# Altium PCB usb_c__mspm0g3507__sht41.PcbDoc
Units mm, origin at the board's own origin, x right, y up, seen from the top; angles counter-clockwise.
Board outline 68 x 40 mm, 2 copper layers (Top, Bottom), stack 0 mm thick; 37 components, 33 nets, 186 pads, 54 vias.
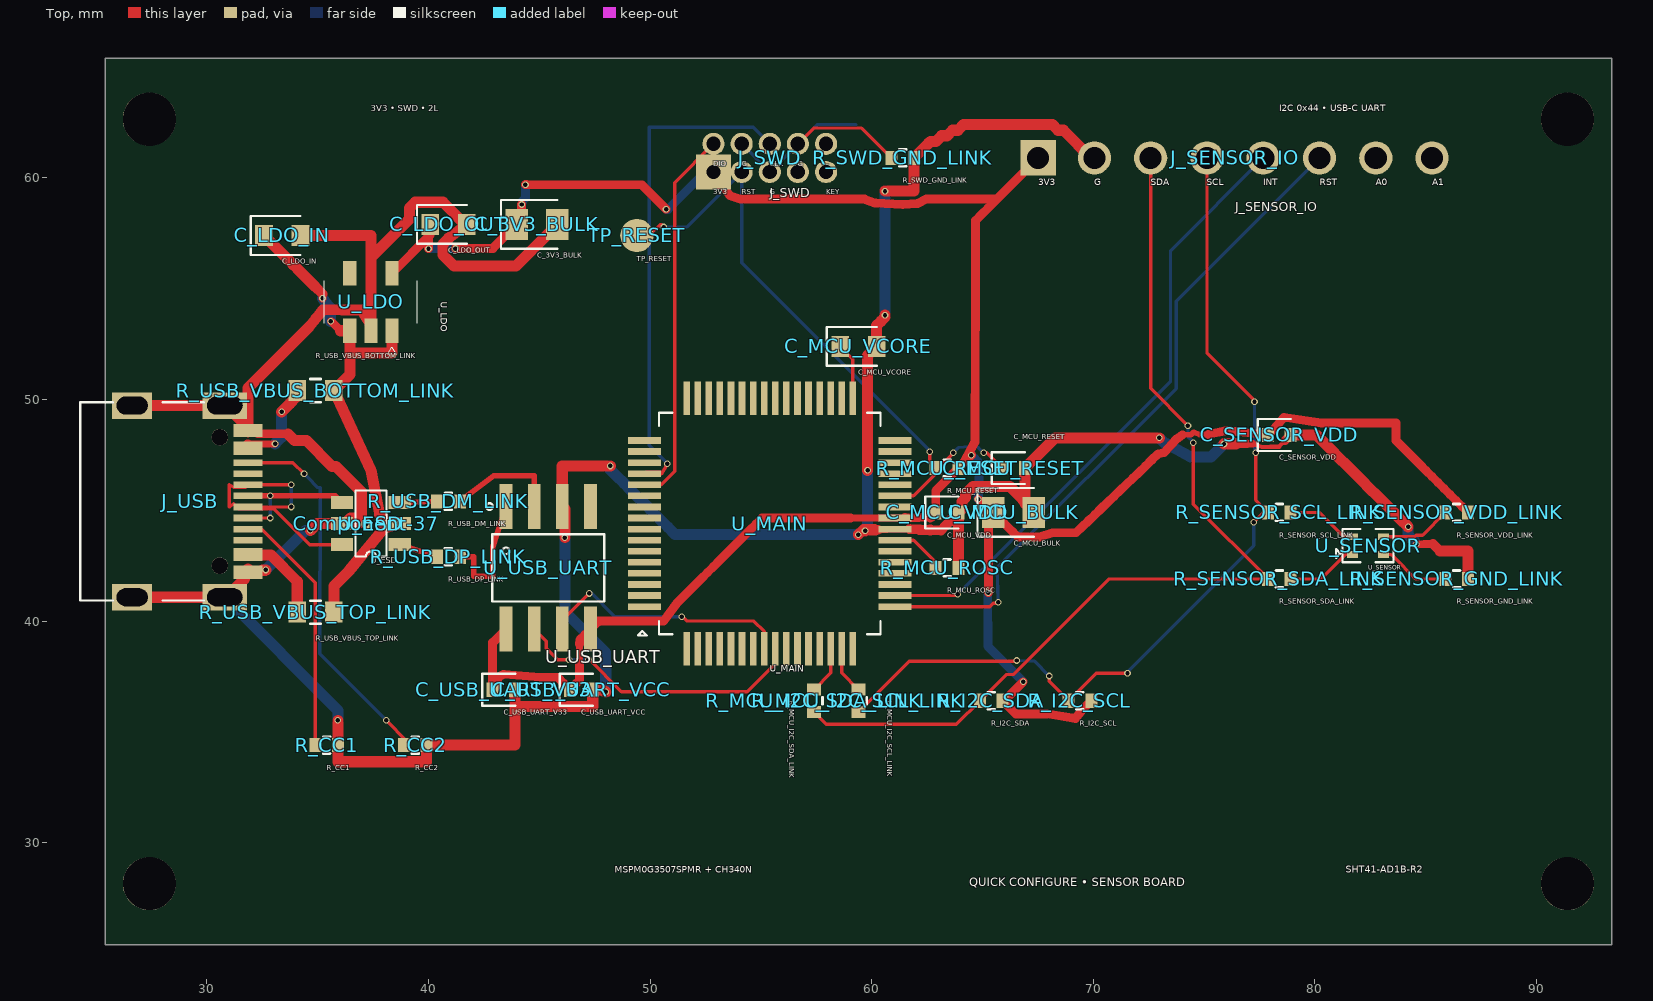
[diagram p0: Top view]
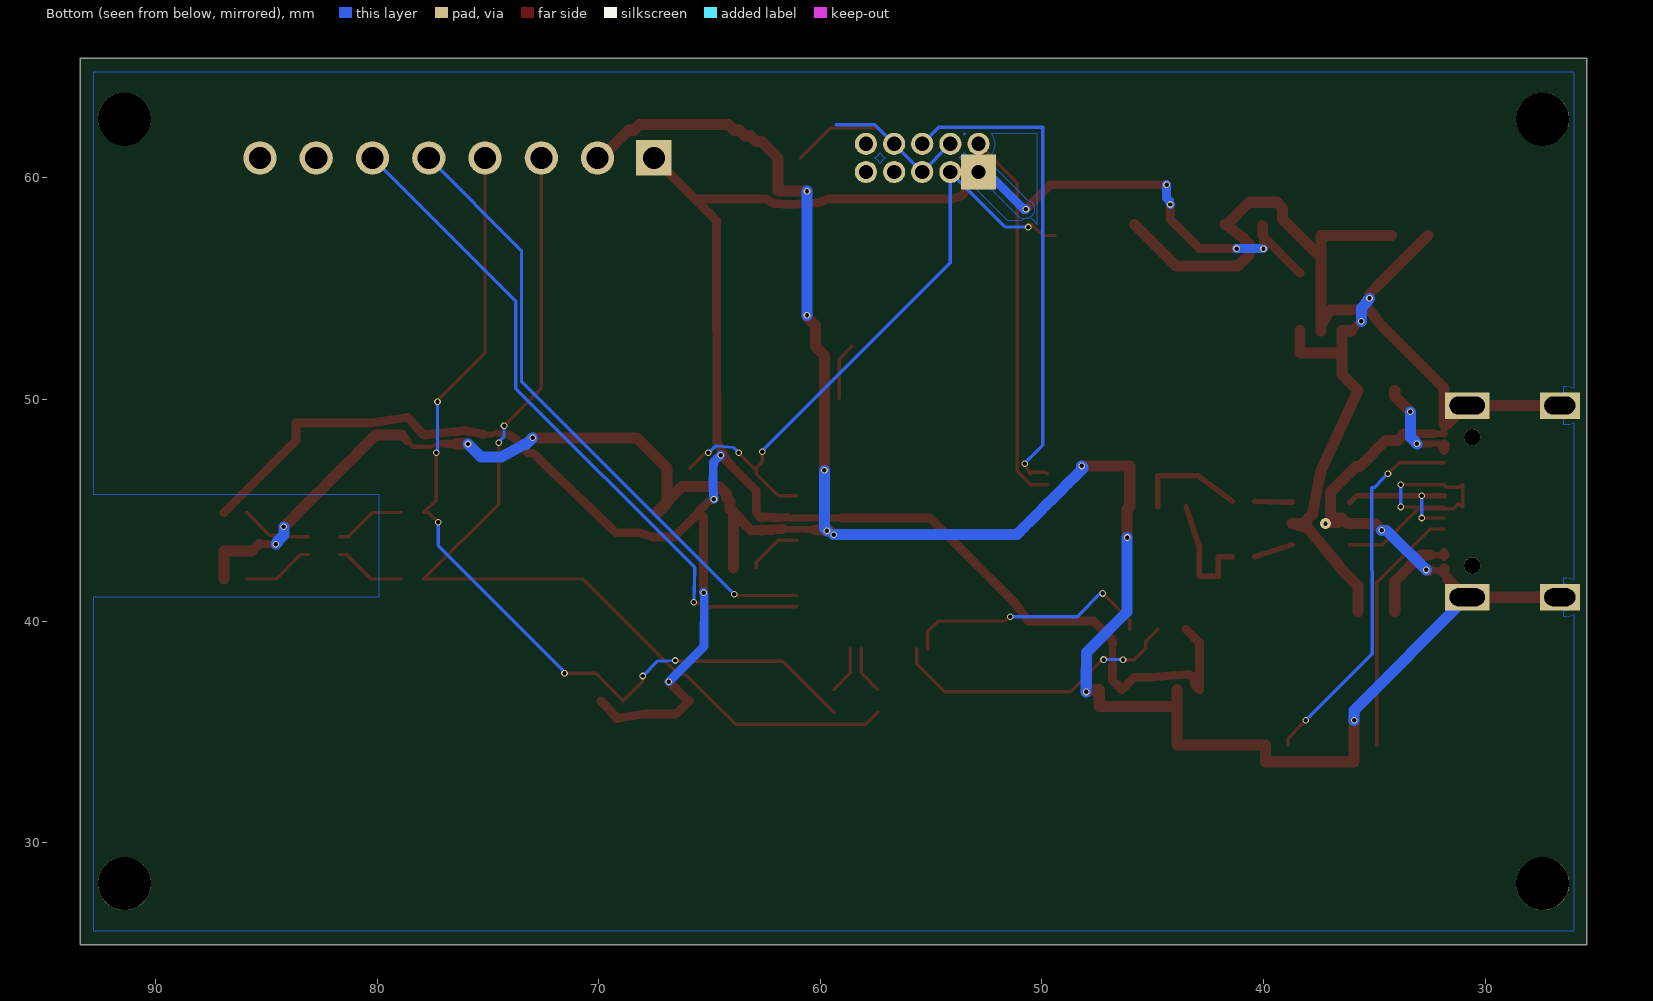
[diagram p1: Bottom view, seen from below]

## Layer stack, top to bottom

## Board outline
25.4,65.4 93.4,65.4 93.4,25.4 25.4,25.4

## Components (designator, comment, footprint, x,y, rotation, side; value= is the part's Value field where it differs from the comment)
C_3V3_BULK "" TSCIRCUIT-2.8500x1.4000mm 44.9,57.9 r0 top
C_LDO_IN "" TSCIRCUIT-2.4500x0.9500mm 33.4,57.4 r0 top
C_LDO_OUT "" TSCIRCUIT-2.4500x0.9500mm 40.9,57.9 r0 top
C_MCU_BULK "" TSCIRCUIT-2.8500x1.4000mm 66.4,44.9 r0 top
C_MCU_RESET "" TSCIRCUIT-1.5600x0.6400mm 66.4,46.9 r0 top
C_MCU_VCORE "" TSCIRCUIT-2.4500x0.9500mm 59.4,52.4 r0 top
C_MCU_VDD "" TSCIRCUIT-1.5600x0.6400mm 63.4,44.9 r0 top
C_SENSOR_VDD "" TSCIRCUIT-1.5600x0.6400mm 78.4,48.4 r0 top
C_USB_UART_V33 "" TSCIRCUIT-1.5600x0.6400mm 43.4,36.9 r0 top
C_USB_UART_VCC "" TSCIRCUIT-1.5600x0.6400mm 46.9,36.9 r0 top
Component-37 "" TSCIRCUIT-0.5000x0.5000mm 37.2,44.4 r0 top
J_SENSOR_IO "" TSCIRCUIT-19.2800x1.5000mm 76.4,60.9 r0 top
J_SWD "" TSCIRCUIT-6.0800x2.2700mm 55.4,60.9 r0 top
J_USB "" TSCIRCUIT-6.7732x9.8502mm 29.112,45.4 r90 top
R_CC1 "" TSCIRCUIT-1.5600x0.6400mm 35.4,34.4 r0 top
R_CC2 "" TSCIRCUIT-1.5600x0.6400mm 39.4,34.4 r0 top
R_I2C_SCL "" TSCIRCUIT-1.5600x0.6400mm 69.4,36.4 r0 top
R_I2C_SDA "" TSCIRCUIT-1.5600x0.6400mm 65.4,36.4 r0 top
R_MCU_I2C_SCL_LINK "" TSCIRCUIT-0.6400x1.5600mm 59.4,36.4 r270 top
R_MCU_I2C_SDA_LINK "" TSCIRCUIT-0.6400x1.5600mm 57.4,36.4 r270 top
R_MCU_RESET "" TSCIRCUIT-1.5600x0.6400mm 63.4,46.9 r0 top
R_MCU_ROSC "" TSCIRCUIT-1.5600x0.6400mm 63.4,42.4 r0 top
R_SENSOR_GND_LINK "" TSCIRCUIT-1.5600x0.6400mm 86.4,41.9 r0 top
R_SENSOR_SCL_LINK "" TSCIRCUIT-1.5600x0.6400mm 78.4,44.9 r0 top
R_SENSOR_SDA_LINK "" TSCIRCUIT-1.5600x0.6400mm 78.4,41.9 r0 top
R_SENSOR_VDD_LINK "" TSCIRCUIT-1.5600x0.6400mm 86.4,44.9 r0 top
R_SWD_GND_LINK "" TSCIRCUIT-1.5600x0.6400mm 61.4,60.9 r0 top
R_USB_DM_LINK "" TSCIRCUIT-1.5600x0.6400mm 40.9,45.4 r0 top
R_USB_DP_LINK "" TSCIRCUIT-1.5600x0.6400mm 40.9,42.9 r0 top
R_USB_VBUS_BOTTOM_LINK "" TSCIRCUIT-2.4500x0.9500mm 34.9,50.4 r0 top
R_USB_VBUS_TOP_LINK "" TSCIRCUIT-2.4500x0.9500mm 34.9,40.4 r0 top
TP_RESET "" TSCIRCUIT-1.5000x1.5000mm 49.4,57.4 r0 top
U_ESD "" TSCIRCUIT-3.6000x2.5000mm 37.4,44.4 r0 top
U_LDO "" TSCIRCUIT-2.5000x3.7000mm 37.4,54.4 r270 top
U_MAIN "" TSCIRCUIT-12.8000x12.8000mm 55.4,44.4 r0 top
U_SENSOR "" TSCIRCUIT-1.9000x1.1001mm 82.4,43.4 r0 top
U_USB_UART "" TSCIRCUIT-4.3840x7.5712mm 45.4,42.4 r0 top

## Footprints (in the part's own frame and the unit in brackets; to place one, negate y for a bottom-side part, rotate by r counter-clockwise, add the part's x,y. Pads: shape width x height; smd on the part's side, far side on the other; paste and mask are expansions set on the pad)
TSCIRCUIT-0.5000x0.5000mm [mm]
TSCIRCUIT-0.6400x1.5600mm [mm]
  rect 0.54x0.64 smd: 1(-0.51,0) 2(0.51,0)
  silkscreen extent -0.15,-0.38 0.15,0.38
TSCIRCUIT-1.5000x1.5000mm [mm]
  round 1.5 smd: 1(0,0)
TSCIRCUIT-1.5600x0.6400mm [mm]
  rect 0.54x0.64 smd: 1(-0.51,0) 2(0.51,0)
  silkscreen extent -0.98,-0.72 0.51,0.72
TSCIRCUIT-1.9000x1.1001mm [mm]
  rect 0.5x0.3 smd: 1(-0.7,-0.4) 2(-0.7,0.4) 3(0.7,0.4) 4(0.7,-0.4)
  silkscreen extent -1.45,-0.75 1.15,0.75
TSCIRCUIT-2.4500x0.9500mm [mm]
  rect 0.8x0.95 smd: 1(-0.825,0) 2(0.825,0)
  silkscreen extent -1.42,-0.87 0.82,0.87
TSCIRCUIT-2.5000x3.7000mm [mm]
  rect 1.1x0.6 smd: 1(1.3,0.95) 2(1.3,0) 3(1.3,-0.95) 4(-1.3,-0.95) 5(-1.3,0.95)
  silkscreen extent -0.95,-2.1 2.35,2.1
TSCIRCUIT-2.8500x1.4000mm [mm]
  rect 1.025x1.4 smd: 1(-0.913,0) 2(0.913,0)
  silkscreen extent -1.62,-1.1 0.91,1.1
TSCIRCUIT-3.6000x2.5000mm [mm]
  rect 1x0.6 smd: 1(-1.3,-0.95) 2(-1.3,0) 3(-1.3,0.95) 4(1.3,0.95) 5(1.3,0) 6(1.3,-0.95)
  silkscreen extent -0.7,-1.49 0.7,1.49
TSCIRCUIT-4.3840x7.5712mm [mm]
  rect 0.574x2.036 smd: 1(-1.905,2.768) 2(-0.635,2.768) 3(0.635,2.768) 4(1.905,2.768) 5(1.905,-2.768) 6(0.635,-2.768) 7(-0.635,-2.768) 8(-1.905,-2.768)
  silkscreen extent -2.79,-1.52 2.53,2.92
TSCIRCUIT-6.0800x2.2700mm [mm]
  rect 1.6x1.6 hole 0.65: 1(-2.54,-0.635)
  round 1 hole 0.65: 2(-2.54,0.635) 3(-1.27,0.635) 4(0,0.635) 5(1.27,0.635) 6(2.54,0.635) 7(2.54,-0.635) 8(1.27,-0.635) 9(0,-0.635) 10(-1.27,-0.635)
TSCIRCUIT-6.7732x9.8502mm [mm]
  rect 0.3x1.3 smd: 1(-3.35,-2.737) 2(-3.05,-2.737) 3(-2.55,-2.737) 4(-2.25,-2.737) 5(-1.75,-2.737) 6(-1.25,-2.737) 7(-0.75,-2.737) 8(-0.25,-2.737) 9(0.25,-2.737) 10(0.75,-2.737) 11(1.25,-2.737) 12(1.75,-2.737) 13(2.55,-2.737) 14(2.25,-2.737) 15(3.35,-2.737) 16(3.05,-2.737)
  rect 1.2x2 hole 0.8 slot 1.6 at 90 deg: 17(-4.325,-1.693) 18(4.325,-1.693)
  rect 1.2x1.8 hole 0.8 slot 1.4 at 90 deg: 19(4.325,2.487) 20(-4.325,2.487)
  round 0.75 hole 0.75 unplated: NPTH-1(-2.9,-1.468) NPTH-2(2.9,-1.468)
  silkscreen extent -4.47,-0.75 4.47,4.83
TSCIRCUIT-12.8000x12.8000mm [mm]
  rect 1.5x0.3 smd: 1(-5.65,-3.75) 2(-5.65,-3.25) 3(-5.65,-2.75) 4(-5.65,-2.25) 5(-5.65,-1.75) 6(-5.65,-1.25) 7(-5.65,-0.75) 8(-5.65,-0.25) 9(-5.65,0.25) 10(-5.65,0.75) 11(-5.65,1.25) 12(-5.65,1.75) 13(-5.65,2.25) 14(-5.65,2.75) 15(-5.65,3.25) 16(-5.65,3.75) 33(5.65,3.75) 34(5.65,3.25) 35(5.65,2.75) 36(5.65,2.25) 37(5.65,1.75) 38(5.65,1.25) 39(5.65,0.75) 40(5.65,0.25) 41(5.65,-0.25) 42(5.65,-0.75) 43(5.65,-1.25) 44(5.65,-1.75) 45(5.65,-2.25) 46(5.65,-2.75) 47(5.65,-3.25) 48(5.65,-3.75)
  rect 0.3x1.5 smd: 17(-3.75,5.65) 18(-3.25,5.65) 19(-2.75,5.65) 20(-2.25,5.65) 21(-1.75,5.65) 22(-1.25,5.65) 23(-0.75,5.65) 24(-0.25,5.65) 25(0.25,5.65) 26(0.75,5.65) 27(1.25,5.65) 28(1.75,5.65) 29(2.25,5.65) 30(2.75,5.65) 31(3.25,5.65) 32(3.75,5.65) 49(3.75,-5.65) 50(3.25,-5.65) 51(2.75,-5.65) 52(2.25,-5.65) 53(1.75,-5.65) 54(1.25,-5.65) 55(0.75,-5.65) 56(0.25,-5.65) 57(-0.25,-5.65) 58(-0.75,-5.65) 59(-1.25,-5.65) 60(-1.75,-5.65) 61(-2.25,-5.65) 62(-2.75,-5.65) 63(-3.25,-5.65) 64(-3.75,-5.65)
  silkscreen extent -5.95,-5.05 5,5
TSCIRCUIT-19.2800x1.5000mm [mm]
  rect 1.6x1.6 hole 1: 1(-8.89,0)
  round 1.5 hole 1: 2(-6.35,0) 3(-3.81,0) 4(-1.27,0) 5(1.27,0) 6(3.81,0) 7(6.35,0) 8(8.89,0)

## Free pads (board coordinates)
  round 2.4 hole 2.4 unplated: NPTH-3(27.4,28.15) NPTH-4(91.4,28.15) NPTH-5(27.4,62.65) NPTH-6(91.4,62.65)

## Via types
v1: diameter 0.3, hole 0.2, Top to Bottom, 53 vias
v2: diameter 0.5, hole 0.2, Top to Bottom, 1 vias

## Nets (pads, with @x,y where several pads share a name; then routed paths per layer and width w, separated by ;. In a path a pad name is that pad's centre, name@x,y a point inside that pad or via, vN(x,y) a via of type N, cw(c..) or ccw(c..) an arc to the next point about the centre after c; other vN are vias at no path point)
".J_SWD > .pin2 to .U_MAIN > .pin12": J_SWD.2 U_MAIN.12 | length 17.1
  Top w0.15: U_MAIN.12 50.495,46.15 51.111,46.762 51.11,59.781 J_SWD.2
".J_SWD > .pin4 to .U_MAIN > .pin13": J_SWD.4 U_MAIN.13 | length 22.7
  Top w0.15: U_MAIN.13 49.819,46.719 50.52,46.719 50.509,46.646 50.708,46.977 v1(50.771,47.106)
  Bottom w0.15: v1(50.771,47.106) 50.77,47.112 49.959,47.923 49.959,62.28 54.655,62.28 J_SWD.4
".U_MAIN > .pin42 to .R_MCU_ROSC > .pin1": R_MCU_ROSC.1 U_MAIN.42 | length 2.5
  Top w0.15: U_MAIN.42 61.89,43.65 62.89,42.65 R_MCU_ROSC.1
GND: C_3V3_BULK.2 C_LDO_IN.2 C_LDO_OUT.2 C_MCU_BULK.2 C_MCU_RESET.2 C_MCU_VCORE.2 C_MCU_VDD.2 C_SENSOR_VDD.2 C_USB_UART_V33.2 C_USB_UART_VCC.2 J_SENSOR_IO.2 J_USB.1 J_USB.2 J_USB.15 J_USB.16 J_USB.17 J_USB.18 J_USB.19 J_USB.20 R_CC1.2 R_CC2.2 R_MCU_ROSC.2 R_SENSOR_GND_LINK.2 R_SWD_GND_LINK.2 U_ESD.2 U_LDO.2 U_MAIN.41 U_USB_UART.3 | length 181.2
  Top w0.188: 77.2,48 77.618,47.858 78.001,47.866
  Top w0.2: 78.001,47.866 78.384,47.874 C_SENSOR_VDD.2@78.647,48.137
  Top w0.275: J_USB.16 J_USB.16@32.299,48.45
  Top w0.3: J_USB.1@31.699,41.9 J_USB.1 J_USB.1@31.849,42.2 ; J_USB.15@31.699,48.9 J_USB.15 ; J_USB.2 31.996,42.25 32.076,42.25 32.118,42.292 J_USB.2@32.499,42.292 ; J_USB.16@31.849,48.6 J_USB.15 ; J_USB.15@31.849,48.9 J_USB.15 ; 60.113,44.15 60.582,44.15 U_MAIN.41 61.144,44.15 61.238,44.15 61.331,44.15 61.425,44.15 61.519,44.15 61.613,44.15 U_MAIN.41@61.706,44.15
  Top w0.301: U_MAIN.41@60.3,44.118 60.425,44.118 60.55,44.118 60.675,44.118 U_MAIN.41
  Top w0.325: J_USB.16 J_USB.16@31.849,48.6
  Top w0.337: 76.936,48.001 77.2,48
  Top w0.35: v1(84.573,43.468) 84.952,43.473 85.331,43.479
  Top w0.375: J_USB.16@32.299,48.45 32.749,48.45 33.199,48.45 ; 76.437,48.001 76.936,48.001
  Top w0.4: 33.199,48.45 33.649,48.45 ; 36.6,44.4 37.2,44.4 ; 60.175,44.118 60.3,44.118 ; C_SENSOR_VDD.2@78.647,48.137 C_SENSOR_VDD.2
  Top w0.437: 63.119,44.087 63.338,44.306 63.556,44.525
  Top w0.45: U_MAIN.41@61.706,44.15 62.177,44.129 ; 62.648,44.108 63.119,44.087 ; 85.331,43.479 85.647,43.163
  Top w0.475: 34.92,53.66 35.228,54.041 35.666,54.041 36.103,54.041 ; v1(59.397,43.902) 59.401,43.907 59.645,44.15 60.113,44.15 ; 62.177,44.129 62.648,44.108
  Top w0.481: 34.613,53.279 34.92,53.66
  Top w0.5: J_USB.20 J_USB.17 ; J_USB.19 J_USB.18 ; J_USB.17 30.874,41.075 31.474,41.675 31.699,41.9 ; J_USB.18 30.874,49.725 31.474,49.125 31.699,48.9 ; J_USB.1@31.849,42.2 J_USB.2 ; 31.849,48.9 31.849,50.516 34.613,53.279 ; 32.499,42.292 32.64,42.292 v1(32.653,42.306) ; 33.649,48.45 33.949,48.15 34.483,48.15 35.65,46.983 35.817,46.983 36.983,45.817 36.983,44.817 36.817,44.65 36.483,44.65 36.233,44.4 U_ESD.2 34.977,44.4 v1(34.668,44.091) ; C_LDO_IN.2 37.4,57.4 U_LDO.2 ; v1(35.91,35.52) 35.91,35.4 R_CC1.2 35.91,33.65 39.91,33.65 R_CC2.2 43.91,34.4 C_USB_UART_V33.2 43.91,36.15 47.41,36.15 C_USB_UART_VCC.2 47.826,36.9 47.885,36.841 47.959,36.841 v1(48,36.8) ; 36.103,54.041 36.541,54.041 36.978,54.041 37.189,53.713 37.4,53.384 U_LDO.2 ; C_3V3_BULK.2 43.937,56.025 41.15,56.025 40.65,56.525 40.65,57.025 40.9,57.275 C_LDO_OUT.2 41.65,57.9 40.65,58.9 39.4,58.9 39.15,58.65 39.15,58.15 37.65,56.65 37.4,56.4 U_LDO.2 ; v1(46.15,43.767) 46.15,45.053 U_USB_UART.3 46.035,47 v1(48.2,47) ; v1(59.7,44.075) 59.645,44.118 60.05,44.118 60.175,44.118 ; v1(59.813,46.799) 59.816,46.802 59.816,46.82 59.816,51.991 C_MCU_VCORE.2 60.225,52.871 60.225,53.342 60.413,53.529 60.6,53.717 v1(60.6,53.8) ; v1(60.6,59.4) 61.91,59.4 R_SWD_GND_LINK.2 62.241,61.231 62.571,61.561 62.65,61.64 62.65,61.65 62.9,61.65 63.15,61.9 63.4,61.9 63.65,62.15 63.9,62.15 64.15,62.4 68.15,62.4 68.4,62.15 68.65,62.15 69.9,60.9 J_SENSOR_IO.2 ; 63.556,44.525 63.66,44.65 C_MCU_VDD.2 ; R_MCU_ROSC.2 C_MCU_VDD.2 ; v1(72.984,48.267) 72.513,48.267 72.043,48.267 71.572,48.267 71.101,48.267 70.63,48.267 70.16,48.267 69.689,48.267 69.218,48.267 68.748,48.267 68.277,48.267 67.935,47.925 67.593,47.583 67.252,47.242 C_MCU_RESET.2 66.91,45.303 C_MCU_BULK.2 67.312,44.988 66.233,46.067 64.567,46.067 64.233,45.733 64.233,45.567 64.067,45.4 64.067,45.067 63.9,44.9 C_MCU_VDD.2 ; v1(75.9,47.99) 75.91,48 75.936,48 75.938,48.001 76.437,48.001 ; C_SENSOR_VDD.2 79.295,48.4 79.68,48.4 80.065,48.4 80.409,48.056 80.753,47.712 81.098,47.367 81.442,47.023 81.786,46.679 82.13,46.335 82.475,45.99 82.819,45.646 83.163,45.302 83.507,44.958 83.851,44.613 84.196,44.269 84.196,44.265 v1(84.212,44.249) ; 85.647,43.163 86.91,43.163 R_SENSOR_GND_LINK.2
  Bottom w0.5: J_USB.17 35.91,35.971 v1(35.91,35.52) ; v1(32.653,42.306) 34.438,44.091 v1(34.668,44.091) ; v1(46.15,43.767) 46.15,40.419 47.994,38.575 47.996,38.131 47.997,37.687 47.999,37.244 v1(48,36.8) ; v1(48.2,47) 48.151,46.951 48.151,46.883 48.482,46.551 48.813,46.22 49.144,45.889 49.476,45.558 49.807,45.227 50.138,44.895 50.469,44.564 50.8,44.233 51.132,43.902 51.618,43.902 52.104,43.902 52.59,43.902 53.076,43.902 53.562,43.902 54.049,43.902 54.535,43.902 55.021,43.902 55.507,43.902 55.993,43.902 56.48,43.902 56.966,43.902 57.452,43.902 57.938,43.902 58.424,43.902 58.911,43.902 v1(59.397,43.902) ; v1(59.7,44.075) 59.813,44.188 v1(59.813,46.799) ; v1(60.6,53.8) 60.6,54.291 60.6,54.782 60.6,55.272 60.6,55.763 60.6,56.254 60.6,56.745 60.6,57.236 60.6,57.726 60.6,58.217 60.6,58.708 60.6,59.199 v1(60.6,59.4) ; v1(72.984,48.267) 73.274,47.977 73.339,47.977 74.4,47.4 75.31,47.4 v1(75.9,47.99) ; v1(84.212,44.249) 84.212,43.885 84.484,43.613 84.484,43.566 v1(84.573,43.468)
MAIN_RESET: C_MCU_RESET.1 J_SWD.10 R_MCU_RESET.1 TP_RESET.1 U_MAIN.38 | length 29.3
  Top w0.15: TP_RESET.1 49.961,57.4 50.448,57.887 50.514,57.887 v1(50.621,57.78) ; U_MAIN.38 61.889,45.65 62.89,46.651 R_MCU_RESET.1@62.89,46.9 ; v1(62.615,47.635) 62.615,47.175 R_MCU_RESET.1 63.006,46.9 63.631,47.525 63.631,47.544 v1(63.678,47.591) ; v1(65.057,47.593) 65.192,47.598 C_MCU_RESET.1
  Bottom w0.15: v1(50.621,57.78) 51.645,57.78 J_SWD.10 54.13,56.173 62.549,47.754 62.549,47.701 v1(62.615,47.635) ; v1(63.678,47.591) 63.915,47.829 64.661,47.898 64.82,47.83 64.82,47.812 64.984,47.648 v1(65.057,47.593)
MCU_I2C_SCL_LOCAL: R_MCU_I2C_SCL_LINK.1 U_MAIN.50 | length 2.2
  Top w0.15: U_MAIN.50 58.65,37.66 R_MCU_I2C_SCL_LINK.1
MCU_I2C_SDA_LOCAL: R_MCU_I2C_SDA_LINK.1 U_MAIN.51 | length 2.2
  Top w0.15: R_MCU_I2C_SDA_LINK.1 58.15,37.66 U_MAIN.51
MSPM0_VCORE: C_MCU_VCORE.1 U_MAIN.32 | length 2.6
  Top w0.15: C_MCU_VCORE.1 59.15,51.825 U_MAIN.32
SENSOR_ADDR0: J_SENSOR_IO.7
SENSOR_ADDR1: J_SENSOR_IO.8
SENSOR_INT: J_SENSOR_IO.5 U_MAIN.47 | length 28.3
  Top w0.15: U_MAIN.47 63.75,41.15 63.785,41.185 63.858,41.185 v1(63.876,41.203)
  Bottom w0.15: v1(63.876,41.203) 73.486,50.816 73.488,56.719 J_SENSOR_IO.5
SENSOR_RESET: J_SENSOR_IO.6 U_MAIN.48 | length 30.8
  Top w0.15: U_MAIN.48 65.331,40.65 65.486,40.805 65.636,40.805 v1(65.704,40.841)
  Bottom w0.15: v1(65.704,40.841) 65.672,42.417 73.751,50.494 73.752,54.439 J_SENSOR_IO.6
SENSOR_SCL: J_SENSOR_IO.4 R_I2C_SCL.1 R_MCU_I2C_SCL_LINK.2 R_SENSOR_SCL_LINK.1 | length 41.7
  Top w0.15: R_MCU_I2C_SCL_LINK.2 61.69,38.18 66.276,38.18 66.505,38.18 v1(66.544,38.219) ; v1(68.01,37.52) 68.01,37.28 R_I2C_SCL.1 70.128,37.638 v1(71.544,37.638) ; J_SENSOR_IO.4 75.13,52.109 77.223,50.017 77.223,49.953 v1(77.276,49.9) ; v1(77.248,44.458) 77.306,44.516 77.69,44.9 R_SENSOR_SCL_LINK.1 77.329,45.461 v1(77.329,47.589)
  Bottom w0.15: v1(66.544,38.219) 67.348,38.182 67.989,37.541 v1(68.01,37.52) ; v1(71.544,37.638) 71.628,37.722 71.628,37.787 77.248,43.406 v1(77.248,44.458) ; v1(77.276,49.9) 77.276,47.706 77.315,47.667 77.315,47.603 v1(77.329,47.589)
SENSOR_SDA: J_SENSOR_IO.3 R_I2C_SDA.1 R_MCU_I2C_SDA_LINK.2 R_SENSOR_SDA_LINK.1 | length 44.6
  Top w0.15: R_MCU_I2C_SDA_LINK.2 57.953,35.337 63.827,35.337 R_I2C_SDA.1 66.076,37.586 66.398,37.586 70.713,41.9 R_SENSOR_SDA_LINK.1 74.513,45.277 v1(74.513,48.04) ; J_SENSOR_IO.3 72.59,50.499 74.251,48.838 v1(74.273,48.816)
  Bottom w0.15: v1(74.273,48.816) 74.273,48.328 74.457,48.143 74.457,48.096 v1(74.513,48.04)
SHT_GND_LOCAL: R_SENSOR_GND_LINK.1 U_SENSOR.4 | length 3.2
  Top w0.15: U_SENSOR.4 83.44,43 83.551,42.891 84.542,41.9 R_SENSOR_GND_LINK.1
SHT_SCL_LOCAL: R_SENSOR_SCL_LINK.2 U_SENSOR.2 | length 3.2
  Top w0.15: R_SENSOR_SCL_LINK.2 80.201,44.9 81.232,43.868 81.291,43.81 81.36,43.8 U_SENSOR.2
SHT_SDA_LOCAL: R_SENSOR_SDA_LINK.2 U_SENSOR.1 | length 3.3
  Top w0.15: R_SENSOR_SDA_LINK.2 80.281,41.9 81.256,42.875 81.313,42.933 81.36,43 U_SENSOR.1
SHT_VDD_LOCAL: R_SENSOR_VDD_LINK.1 U_SENSOR.3 | length 3.2
  Top w0.15: U_SENSOR.3 83.44,43.8 83.5,43.801 83.6,43.801 84.499,43.812 84.571,43.87 84.86,43.87 R_SENSOR_VDD_LINK.1
swd-ground-1-to-2: J_SWD.3 J_SWD.5 J_SWD.9 R_SWD_GND_LINK.1 | length 14.6
  Top w0.15: J_SWD.5 57.382,62.247 59.375,62.247 59.543,62.247 R_SWD_GND_LINK.1
  Bottom w0.15: J_SWD.3 J_SWD.9 57.54,62.405 ; J_SWD.5 57.54,62.405 ; 57.54,62.405 59.277,62.405 57.54,62.405
UART_MSP_RX: U_MAIN.57 U_USB_UART.6 | length 11.5
  Top w0.15: U_USB_UART.6 46.035,40.034 v1(47.247,41.246) ; v1(51.43,40.198) 51.459,40.169 51.5,40.169 51.669,40 54.679,40 55.15,39.529 U_MAIN.57
  Bottom w0.15: v1(47.247,41.246) 47.292,41.291 47.318,41.291 48.411,40.198 v1(51.43,40.198)
UART_MSP_TX: U_MAIN.56 U_USB_UART.7 | length 13.5
  Top w0.15: U_USB_UART.7 45.314,39.083 45.314,38.765 45.83,38.249 v1(46.338,38.249) ; v1(47.217,38.262) 47.194,38.265 47.247,38.265 48.707,36.806 54.392,36.806 55.65,38.064 U_MAIN.56
  Bottom w0.15: v1(46.338,38.249) 46.348,38.259 46.444,38.259 46.447,38.262 v1(47.217,38.262)
usb-dm-device: R_USB_DM_LINK.1 U_ESD.4 | length 1.7
  Top w0.25: U_ESD.4 R_USB_DM_LINK.1
usb-dm-port-tie: J_USB.7 J_USB.9 U_ESD.3 | length 7.4
  Top w0.15: J_USB.7 v1(32.85,44.65) ; J_USB.9 v1(32.85,45.65)
  Top w0.25: J_USB.9 35.8,45.65 U_ESD.3
  Bottom w0.15: v1(32.85,44.65) v1(32.85,45.65)
usb-dm-uart: R_USB_DM_LINK.2 U_USB_UART.2 | length 5.1
  Top w0.25: R_USB_DM_LINK.2 42.95,46.55 44.765,46.55 U_USB_UART.2
usb-dp-device: R_USB_DP_LINK.1 U_ESD.6 | length 1.8
  Top w0.25: U_ESD.6 R_USB_DP_LINK.1
usb-dp-port-tie: J_USB.8 J_USB.10 U_ESD.1 | length 12.7
  Top w0.15: J_USB.8 v1(33.8,45.15) ; v1(33.8,46.15) J_USB.10 31.742,46.043 31.199,46.043 31.013,46.15 31.013,45.15 31.199,45.293 31.427,45.066 33.019,45.066 34.635,43.45 U_ESD.1
  Bottom w0.15: v1(33.8,45.15) v1(33.8,46.15)
usb-dp-uart: R_USB_DP_LINK.2 U_USB_UART.1 | length 5.6
  Top w0.25: R_USB_DP_LINK.2 42.05,42.9 42.05,42.03 42.9,42.03 42.9,43.35 U_USB_UART.1
USB_CC1: J_USB.6 R_CC1.1 | length 11.4
  Top w0.15: J_USB.6 32.463,44.15 34.89,41.723 R_CC1.1
USB_CC2: J_USB.12 R_CC2.1 | length 16.9
  Top w0.15: J_USB.12 33.879,47.15 v1(34.382,46.647) ; v1(38.09,35.52) 38.232,35.378 38.89,34.72 R_CC2.1
  Bottom w0.15: v1(34.382,46.647) 34.542,46.487 34.545,46.487 35.007,46.025 35.112,46.025 35.095,38.524 v1(38.09,35.52)
USB_VBUS_BOTTOM_LOCAL: J_USB.13 J_USB.14 R_USB_VBUS_BOTTOM_LINK.1 | length 4.4
  Top w0.3: J_USB.14 J_USB.14@31.849,47.8 ; J_USB.13 31.893,47.994 32.286,47.994 J_USB.13@32.499,47.994
  Top w0.325: 32.499,47.994 32.68,47.994 v1(33.073,47.994)
  Top w0.475: J_USB.13@31.849,47.8 J_USB.13
  Top w0.5: v1(33.372,49.443) 33.395,49.466 33.735,49.806 34.075,50.146 R_USB_VBUS_BOTTOM_LINK.1
  Bottom w0.5: v1(33.073,47.994) 33.124,48.045 33.124,48.047 33.372,48.295 33.372,48.678 33.372,49.06 v1(33.372,49.443)
USB_VBUS_TOP_LOCAL: J_USB.3 J_USB.4 R_USB_VBUS_TOP_LINK.1 | length 4.5
  Top w0.3: J_USB.3@31.849,42.965 J_USB.3 31.849,43 J_USB.4
  Top w0.318: J_USB.3@31.849,42.965 J_USB.3@32.499,42.974
  Top w0.5: 32.499,42.974 32.887,42.98 34.075,41.792 R_USB_VBUS_TOP_LINK.1
VBUS5: C_LDO_IN.1 R_USB_VBUS_BOTTOM_LINK.2 R_USB_VBUS_TOP_LINK.2 U_ESD.5 U_LDO.1 U_LDO.3 | length 25.5
  Top w0.325: v1(35.584,53.531) 35.601,53.514 v1@35.622,53.514
  Top w0.35: v1(35.214,54.561) 35.214,54.761
  Top w0.375: v1@35.622,53.514 35.829,53.307 36.036,53.1
  Top w0.45: 34.884,55.091 35.214,54.761
  Top w0.5: C_LDO_IN.1 32.905,57.07 33.235,56.74 33.565,56.41 33.894,56.08 34.224,55.751 34.554,55.421 34.884,55.091 ; R_USB_VBUS_TOP_LINK.2 35.725,40.793 35.725,41.185 35.725,41.578 36.069,41.922 36.413,42.266 38,44.2 U_ESD.5 38.2,44.4 37.8,44.8 37.4,46.8 R_USB_VBUS_BOTTOM_LINK.2 36.45,51.125 U_LDO.3 ; 36.036,53.1 U_LDO.3 ; U_LDO.1 38.35,52.1 36.45,52.1 U_LDO.3
  Bottom w0.5: v1(35.214,54.561) 35.304,54.471 35.304,54.414 35.584,54.134 35.584,53.832 v1(35.584,53.531)
VCC_3V3: C_3V3_BULK.1 C_LDO_OUT.1 C_MCU_BULK.1 C_MCU_VDD.1 C_SENSOR_VDD.1 C_USB_UART_V33.1 C_USB_UART_VCC.1 J_SENSOR_IO.1 J_SWD.1 R_I2C_SCL.2 R_I2C_SDA.2 R_MCU_RESET.2 R_SENSOR_VDD_LINK.2 U_LDO.5 U_MAIN.40 U_USB_UART.5 U_USB_UART.8 | length 130.2
  Top w0.25: 74.026,48.406 74.4,48.4 74.525,48.525 74.806,48.419
  Top w0.262: 74.806,48.419 75.196,48.426
  Top w0.3: 46.814,38.642 46.815,38.316 46.815,37.99 ; U_MAIN.40@60.3,44.65 U_MAIN.40@60.34,44.65 ; U_MAIN.40@60.65,44.65 U_MAIN.40 ; U_MAIN.40@61.76,44.65 61.405,44.65 U_MAIN.40 ; U_MAIN.40@60.34,44.65 U_MAIN.40@60.695,44.65 ; U_MAIN.40@60.34,44.65 U_MAIN.40@60.695,44.65 ; U_MAIN.40@60.695,44.65 U_MAIN.40 ; U_MAIN.40@60.695,44.65 U_MAIN.40
  Top w0.301: 60.25,44.65 U_MAIN.40@60.65,44.65
  Top w0.312: 46.814,38.642 46.813,38.968 ; 59.85,44.65 60.25,44.65 ; 60.3,44.65 59.985,44.65 U_MAIN.40@60.34,44.65
  Top w0.325: 59.051,44.651 59.45,44.651 59.85,44.65
  Top w0.344: U_MAIN.40@61.5,44.7 61.479,44.663 U_MAIN.40@61.791,44.672
  Top w0.35: U_MAIN.40@61.5,44.7 61.807,44.675 62.115,44.65 U_MAIN.40@61.76,44.65
  Top w0.363: v1(64.8,45.5) 65.061,45.384 C_MCU_BULK.1@65.274,45.17
  Top w0.375: U_MAIN.40@61.791,44.672 62.102,44.682
  Top w0.387: 58.651,44.651 59.051,44.651
  Top w0.4: U_LDO.5 40.075,57.425 C_LDO_OUT.1 40,57.825 v1(40,56.8) ; v1(41.214,56.81) 41.224,56.82 41.435,56.82 42.907,56.82 C_3V3_BULK.1 44.205,58.117 v1(44.2,58.8) ; U_USB_UART.8 42.89,39.027 C_USB_UART_V33.1 43.123,37.133 43.123,37.462 43.4,37.6 45.055,37.462 45.442,37.462 45.828,37.462 46.109,37.181 C_USB_UART_VCC.1 46.603,37.119 46.817,37.338 46.816,37.664 46.815,37.99 ; v1(44.373,59.698) 44.394,59.698 44.425,59.703 49.639,59.674 v1(50.72,58.59) ; 46.813,38.968 46.828,39.155 47.067,39.394 U_USB_UART.5 47.489,39.816 47.673,40 48.063,40 48.453,40 48.842,40 49.232,40 49.622,40 50.012,40 50.402,40 50.6,40 51.222,40.821 51.496,41.095 51.769,41.368 52.043,41.642 52.316,41.916 52.59,42.189 52.863,42.463 53.137,42.737 53.411,43.01 53.684,43.284 53.958,43.557 54.231,43.831 54.505,44.105 54.778,44.378 55.052,44.652 55.452,44.652 55.851,44.652 56.251,44.652 56.651,44.652 57.051,44.651 57.451,44.651 57.851,44.651 58.251,44.651 58.651,44.651 ; J_SWD.1 53.6,59.2 54.083,59.042 54.482,59.042 54.881,59.042 55.28,59.042 55.679,59.042 56.078,59.042 56.477,59.042 56.876,59.042 57.275,59.042 57.673,59.042 58.072,59.042 58.471,59.042 58.87,59.042 59.269,59.042 59.668,59.042 60.164,58.86 61.4,58.8 62.074,58.847 62.46,59.042 62.859,59.042 63.258,59.042 63.657,59.042 64.056,59.042 64.455,59.042 64.854,59.042 65.253,59.042 65.652,59.042 65.917,59.307 66.183,59.573 66.448,59.838 66.714,60.104 66.979,60.369 67.245,60.635 J_SENSOR_IO.1 67.228,60.618 66.946,60.336 66.663,60.053 66.381,59.771 66.099,59.489 65.817,59.207 65.534,58.924 65.252,58.642 64.97,58.36 64.688,58.078 64.687,57.678 64.686,57.278 64.685,56.878 64.684,56.478 64.683,56.079 64.682,55.679 64.681,55.279 64.681,54.879 64.68,54.479 64.679,54.08 64.678,53.68 64.677,53.28 64.676,52.88 64.675,52.48 64.674,52.081 64.673,51.681 64.673,51.281 64.672,50.881 64.671,50.481 64.67,50.082 64.669,49.682 64.668,49.282 64.667,48.882 64.666,48.482 64.666,48.083 64.162,47.161 R_MCU_RESET.2 ; 62.102,44.682 62.414,44.691 62.725,44.7 62.64,44.65 C_MCU_VDD.1 62.89,45.88 R_MCU_RESET.2 ; v1(64.5,47.489) 64.303,47.293 64.107,47.096 R_MCU_RESET.2 ; v1(65.265,41.28) 65.265,44.677 C_MCU_BULK.1 ; C_MCU_BULK.1@65.274,45.17 65.487,44.957 C_MCU_BULK.1 ; v1(66.843,37.258) 66.816,37.231 65.985,36.4 R_I2C_SDA.2 66.106,36.204 66.302,36.008 66.498,35.812 66.851,35.812 67.204,35.812 67.557,35.812 67.91,35.812 69.2,35.6 69.518,36.008 69.714,36.204 R_I2C_SCL.2 ; 74.026,48.406 73.756,48.21 73.2,47.6 72.93,47.544 72.645,47.27 72.359,46.996 72.074,46.722 71.789,46.449 71.503,46.175 71.218,45.901 70.932,45.627 70.647,45.353 70.361,45.079 70.076,44.805 69.791,44.531 69.505,44.257 69.22,43.983 68.868,43.983 68.516,43.983 68.164,43.983 67.6,43.8 66.6,43.8 66.405,43.983 66.175,44.213 65.946,44.442 65.717,44.671 C_MCU_BULK.1 ; 75.196,48.426 76.044,48.598 76.413,48.558 76.783,48.519 77.152,48.479 77.521,48.44 C_SENSOR_VDD.1 78.16,48.67 78.6,49.2 80.3,48.939 80.674,48.939 81.048,48.939 81.422,48.939 81.796,48.939 82.17,48.939 82.544,48.939 82.918,48.939 83.292,48.939 83.667,48.939 83.667,48.541 83.667,48.143 83.937,47.873 84.207,47.603 84.477,47.333 84.748,47.062 85.018,46.792 85.288,46.522 85.559,46.251 85.829,45.981 86.099,45.711 86.369,45.441 86.64,45.17 R_SENSOR_VDD_LINK.2
  Bottom w0.4: v1(40,56.8) 40.001,56.801 40.219,56.801 40.228,56.81 v1(41.214,56.81) ; v1(44.2,58.8) 44.24,58.902 44.24,58.963 44.375,59.098 v1(44.373,59.698) ; v1(50.72,58.59) 50.738,58.575 50.801,58.575 52.492,60.265 J_SWD.1 ; v1(64.5,47.489) 64.662,47.329 64.824,47.168 64.829,46.773 64.835,46.377 64.84,45.982 v1(64.8,45.5) ; v1(65.265,41.28) 65.237,41.116 65.247,38.865 v1(66.843,37.258)
pads on no net: J_SWD.6 J_SWD.7 J_SWD.8 J_USB.5 J_USB.11 J_USB.NPTH-1 J_USB.NPTH-2 U_LDO.4 U_MAIN.1 U_MAIN.2 U_MAIN.3 U_MAIN.4 U_MAIN.5 U_MAIN.6 U_MAIN.7 U_MAIN.8 U_MAIN.9 U_MAIN.10 U_MAIN.11 U_MAIN.14 U_MAIN.15 U_MAIN.16 U_MAIN.17 U_MAIN.18 U_MAIN.19 U_MAIN.20 U_MAIN.21 U_MAIN.22 U_MAIN.23 U_MAIN.24 U_MAIN.25 U_MAIN.26 U_MAIN.27 U_MAIN.28 U_MAIN.29 U_MAIN.30 U_MAIN.31 U_MAIN.33 U_MAIN.34 U_MAIN.35 U_MAIN.36 U_MAIN.37 U_MAIN.39 U_MAIN.43 U_MAIN.44 U_MAIN.45 U_MAIN.46 U_MAIN.49 U_MAIN.52 U_MAIN.53 U_MAIN.54 U_MAIN.55 U_MAIN.58 U_MAIN.59 U_MAIN.60 U_MAIN.61 U_MAIN.62 U_MAIN.63 U_MAIN.64 U_USB_UART.4
copper on no net:
  other v2: 37.2,44.4

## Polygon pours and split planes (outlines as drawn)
GND on Bottom (solid): 92.8,64.8 26,64.8 26,50.51 26.001,50.51 26.16,50.559 26.326,50.575 26.476,50.575 26.476,50.325 26.326,50.325 26.209,50.314 26.096,50.279 26,50.228 26,49.222 26.096,49.171 26.209,49.137 26.326,49.125 26.476,49.125 26.476,48.875 26.326,48.875 26.16,48.891 26.001,48.94 26,48.94 26,41.86 26.001,41.86 26.16,41.909 26.326,41.925 26.476,41.925 26.476,41.675 26.326,41.675 26.209,41.663 26.096,41.629 26,41.578 26,40.572 26.096,40.521 26.209,40.486 26.326,40.475 26.476,40.475 26.476,40.225 26.326,40.225 26.16,40.241 26.001,40.29 26,40.29 26,26 92.8,26 92.8,41.1 80.2,41.1 79.9,41.1 79.9,41.4 79.9,45.1 79.9,45.7 80.5,45.7 92.8,45.7
GND on Bottom (solid): 53.55,62.005 53.44,62.005 53.484,61.952 53.495,61.93 53.506,61.952
GND on Bottom (solid): 53.495,61.14 53.484,61.118 53.399,61.015 53.591,61.015 53.506,61.118
GND on Bottom (solid): 53.61,60.996 53.61,60.804 53.713,60.889 53.735,60.9 53.713,60.911
GND on Bottom (solid): 57.305,61.14 57.294,61.118 57.2,61.005 57.087,60.911 57.065,60.9 57.087,60.889 57.2,60.795 57.294,60.682 57.305,60.66 57.316,60.682 57.41,60.795 57.523,60.889 57.545,60.9 57.523,60.911 57.41,61.005 57.316,61.118
GND on Bottom (solid): 52.28,62.005 50.234,62.005 50.234,57.874 50.251,57.933 50.288,58.002 50.338,58.063 50.399,58.113 50.468,58.15 50.543,58.172 50.621,58.18 50.699,58.172 50.774,58.15 50.843,58.113 50.904,58.063 50.91,58.055 51.531,58.055 52.991,59.515 52.307,59.515 51.084,58.292 51.024,58.242 50.954,58.205 50.879,58.182 50.801,58.175 50.738,58.175 50.66,58.182 50.585,58.205 50.516,58.242 50.486,58.267 50.484,58.266 50.466,58.281 50.467,58.283 50.456,58.292 50.455,58.292 50.437,58.307 50.387,58.368 50.35,58.437 50.327,58.512 50.32,58.59 50.327,58.668 50.35,58.743 50.387,58.812 50.437,58.873 50.497,58.923 50.567,58.96 50.642,58.982 50.643,58.982 52.11,60.449 52.11,61.015 52.321,61.015 52.236,61.118 52.167,61.248 52.124,61.389 52.11,61.535 52.124,61.681 52.167,61.822 52.236,61.952

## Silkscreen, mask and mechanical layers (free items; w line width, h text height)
Top Overlay:
  text "3V3 • SWD • 2L" at 37.4,62.9 h0.48
  text "I2C 0x44 • USB-C UART" at 78.4,62.9 h0.5
  text "MSPM0G3507SPMR + CH340N" at 48.4,28.525 h0.52
  text "SHT41-AD1B-R2" at 81.4,28.525 h0.55
  text "QUICK CONFIGURE • SENSOR BOARD" at 64.4,27.9 h0.65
